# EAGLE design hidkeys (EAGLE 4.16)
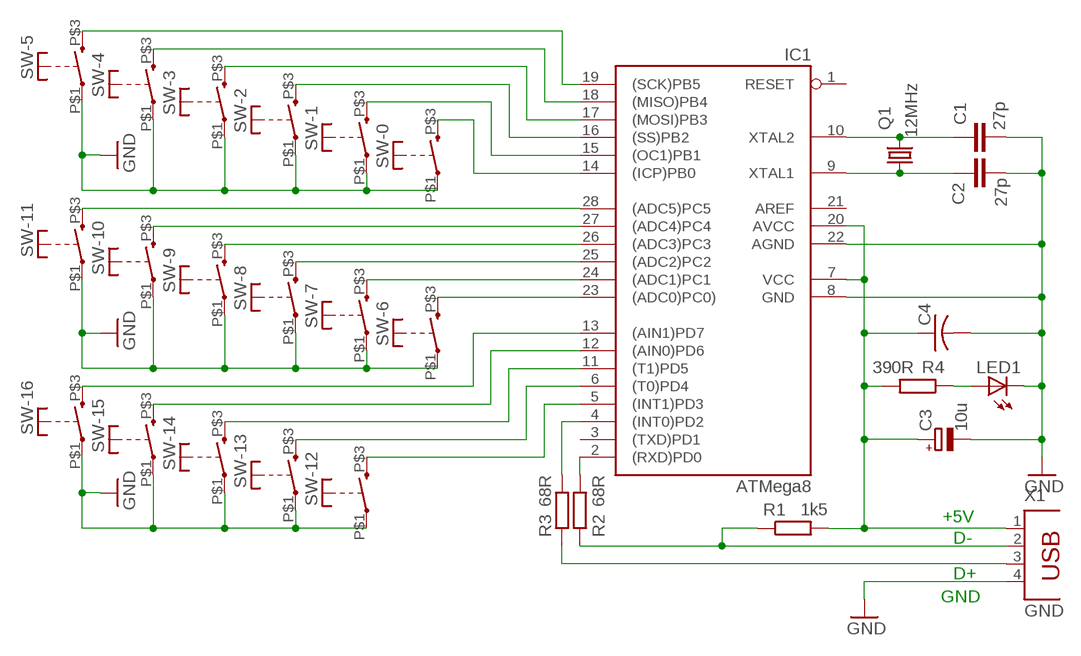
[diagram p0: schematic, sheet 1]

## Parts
C1  27p  C-EU025-024X044  [C025-024X044]
C2  27p  C-EU025-024X044  [C025-024X044]
C3  10u  CPOL-EUE2.5-5  [E2,5-5]
C4  C-US025-024X044  [C025-024X044]
IC1  ATMega8  AT90S4433P  [DIL28-3]
LED1  LED3MM  [LED3MM]
Q1  12MHz  CRYTALHC49S  [HC49/S]
R1  1k5  R-EU_0204/5  [0204/5]
R2  68R  R-EU_0204/5  [0204/5]
R3  68R  R-EU_0204/5  [0204/5]
R4  390R  R-EU_0204/5  [0204/5]
SW-0  DT  [AKI-DIP-SW]
SW-1  DT  [AKI-DIP-SW]
SW-2  DT  [AKI-DIP-SW]
SW-3  DT  [AKI-DIP-SW]
SW-4  DT  [AKI-DIP-SW]
SW-5  DT  [AKI-DIP-SW]
SW-6  DT  [AKI-DIP-SW]
SW-7  DT  [AKI-DIP-SW]
SW-8  DT  [AKI-DIP-SW]
SW-9  DT  [AKI-DIP-SW]
SW-10  DT  [AKI-DIP-SW]
SW-11  DT  [AKI-DIP-SW]
SW-12  DT  [AKI-DIP-SW]
SW-13  DT  [AKI-DIP-SW]
SW-14  DT  [AKI-DIP-SW]
SW-15  DT  [AKI-DIP-SW]
SW-16  DT  [AKI-DIP-SW]
X1  GND  PN61729  [PN61729]

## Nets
GND: C1.2 C2.2 C3.- C4.2 IC1.8(GND) IC1.22(AGND) LED1.K(C) SW-0.P$1(P) SW-1.P$1(P) SW-2.P$1(P) SW-3.P$1(P) SW-4.P$1(P) SW-5.P$1(P) SW-6.P$1(P) SW-7.P$1(P) SW-8.P$1(P) SW-9.P$1(P) SW-10.P$1(P) SW-11.P$1(P) SW-12.P$1(P) SW-13.P$1(P) SW-14.P$1(P) SW-15.P$1(P) SW-16.P$1(P) X1.4
N$1: IC1.19((SCK)PB5) SW-5.P$3(S)
N$2: IC1.18((MISO)PB4) SW-4.P$3(S)
N$4: IC1.16((SS)PB2) SW-2.P$3(S)
N$5: IC1.15((OC1)PB1) SW-1.P$3(S)
N$6: IC1.14((ICP)PB0) SW-0.P$3(S)
N$7: IC1.28((ADC5)PC5) SW-11.P$3(S)
N$8: IC1.27((ADC4)PC4) SW-10.P$3(S)
N$9: IC1.26((ADC3)PC3) SW-9.P$3(S)
N$10: IC1.25((ADC2)PC2) SW-8.P$3(S)
N$11: IC1.24((ADC1)PC1) SW-7.P$3(S)
N$12: IC1.23((ADC0)PC0)) SW-6.P$3(S)
N$13: IC1.13((AIN1)PD7) SW-16.P$3(S)
N$14: IC1.12((AIN0)PD6) SW-15.P$3(S)
N$15: IC1.11((T1)PD5) SW-14.P$3(S)
N$16: IC1.6((T0)PD4) SW-13.P$3(S)
N$17: IC1.5((INT1)PD3) SW-12.P$3(S)
N$18: R1.1 R2.1 X1.2
N$19: R3.1 X1.3
N$20: IC1.4((INT0)PD2) R3.2
N$21: C1.1 IC1.10(XTAL2) Q1.2
N$22: C2.1 IC1.9(XTAL1) Q1.1
N$23: IC1.2((RXD)PD0) R2.2
N$24: LED1.A R4.1
N$26: IC1.17((MOSI)PB3) SW-3.P$3(S)
VCC: C3.+ C4.1 IC1.7(VCC) IC1.20(AVCC) R1.2 R4.2 X1.1
Unconnected: IC1.1(RESET) IC1.3((TXD)PD1)

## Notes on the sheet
- +5V
- D-
- D+
- GND

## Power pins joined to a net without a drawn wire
AREF: IC1.21(AREF)

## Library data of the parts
C1 C2 = rcl:C-EU: CAPACITOR, European symbol
C3 = rcl:CPOL-EU: POLARIZED CAPACITOR, European symbol
C4 = 05 myrcl:C-US: CAPACITOR, American symbol
IC1 = atmel:AT90S4433: MICROCONTROLLER 4 Kbytes FLASH 128 bytes SRAM 256 bytes EEPROM UART 6-channel 10 bit ADC
LED1 = 35 led:LED: LED
Q1 = crystal:CRYTAL: CRYSTAL
R1-R4 = rcl:R-EU_: RESISTOR, European symbol
SW-0 SW-1-SW-16 = 01 MyLibs:DT: ITT SWITCH
X1 = con-berg:PN61729: BERG USB connector

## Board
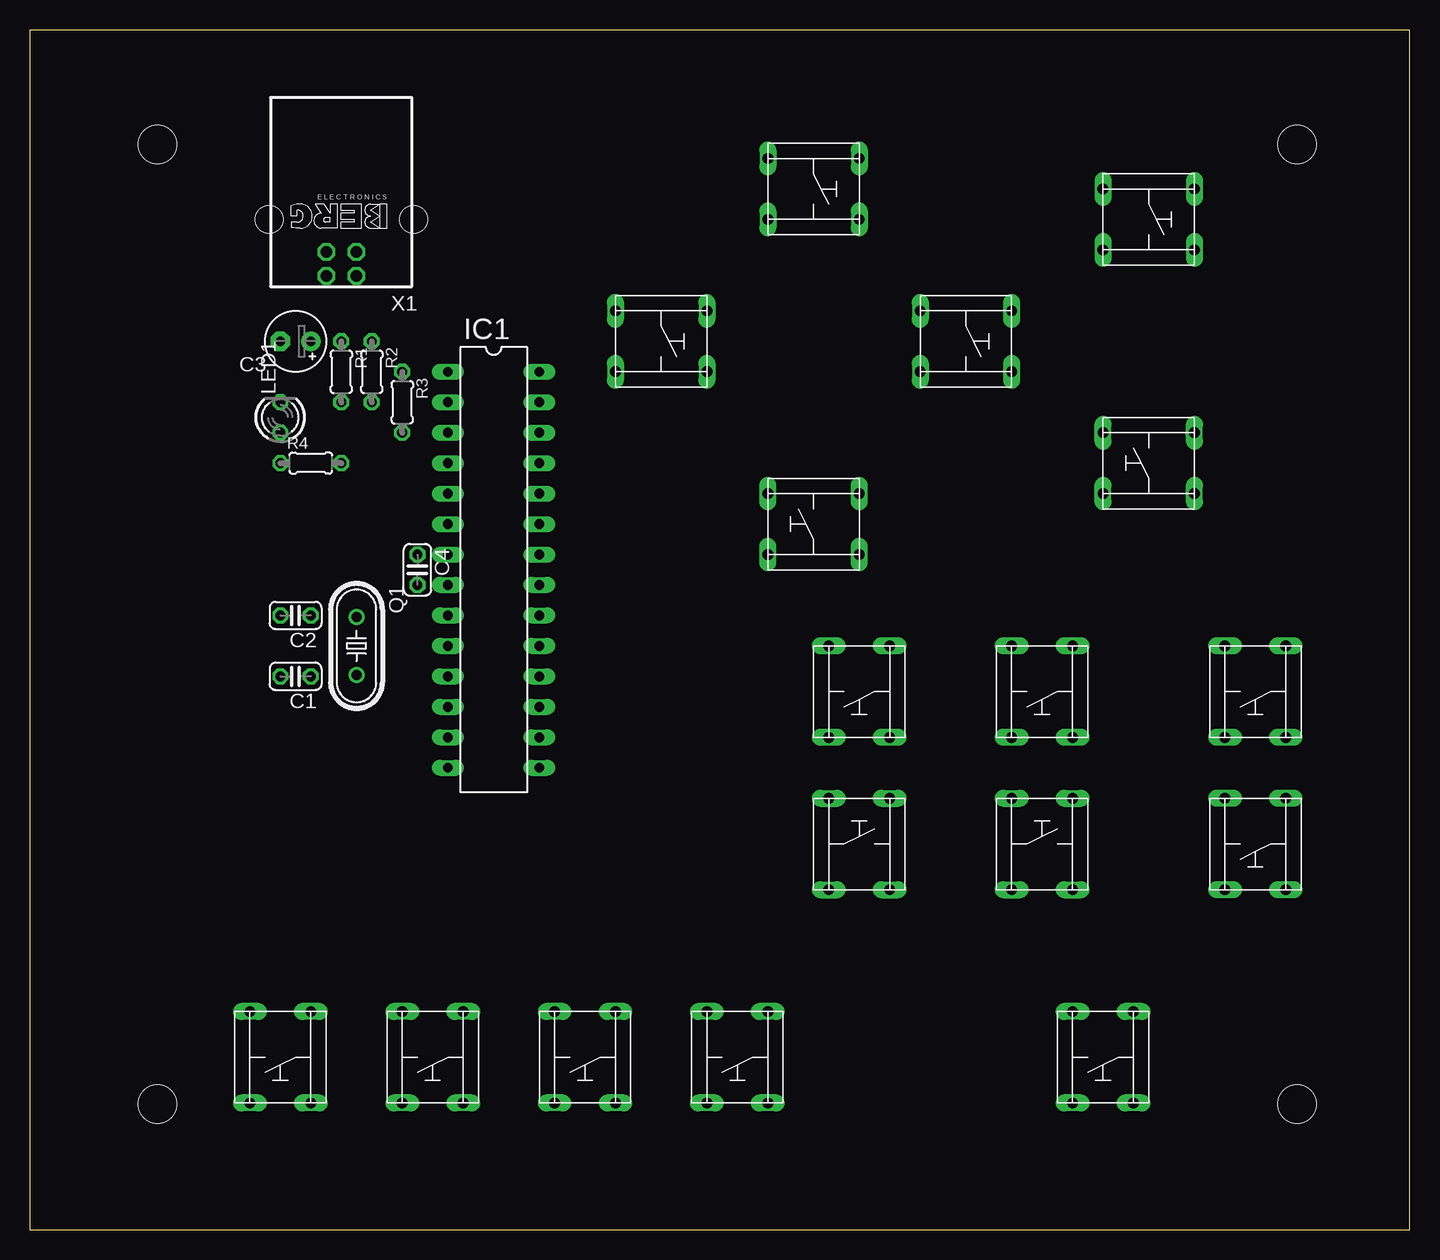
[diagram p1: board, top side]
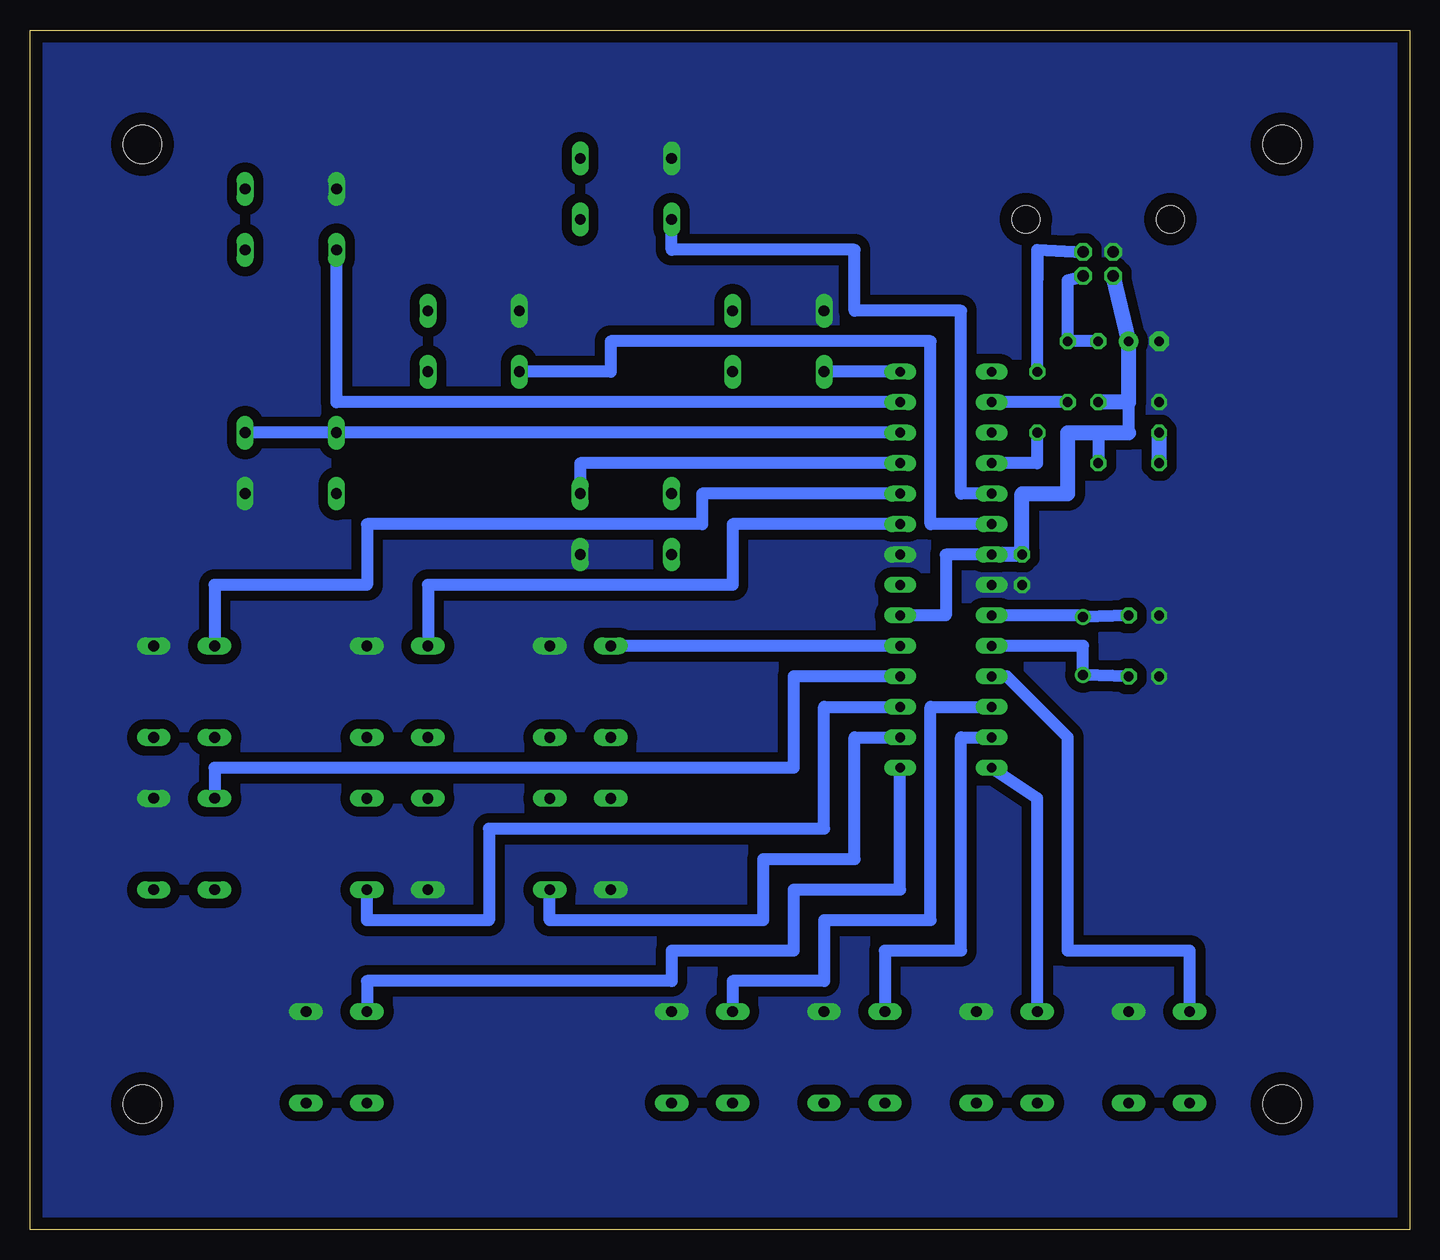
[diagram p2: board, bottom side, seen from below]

Size 115 x 100 mm. Coordinates in mm from the lower left corner, seen from the top.
Outline: 0,0 115,0 115,100 0,100 0,0
Copper layers (1*16): Top 0.035mm / dielectric 1.5mm / Bottom 0.035mm
Design rules "default": minimum track width 10mil, minimum drill 24mil, track to track 8mil, track to pad 8mil, pad to pad 8mil, via to via 8mil, smd to smd 8mil, copper to edge 40mil, drill to drill 8mil, minimum pad ring 10mil, minimum via ring 8mil, stop-mask expansion 4mil, vias tented up to drill 0mil, thermal gap 10mil
Holes 3.2 mm at 10.63,90.47 10.63,10.47 105.63,90.47 105.63,10.47

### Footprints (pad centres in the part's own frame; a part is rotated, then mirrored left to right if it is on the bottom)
C025-024X044 = drill 0.813 octagon: 1 -1.27,0; 2 1.27,0
E2,5-5 = drill 0.813 pad 1.6 round: + -1.27,0 | drill 0.813 pad 1.6 octagon: - 1.27,0
DIL28-3 = drill 0.813 long: 1 -16.51,-3.81; 2 -13.97,-3.81; 3 -11.43,-3.81; 4 -8.89,-3.81; 5 -6.35,-3.81; 6 -3.81,-3.81; 7 -1.27,-3.81; 8 1.27,-3.81; 9 3.81,-3.81; 10 6.35,-3.81; 11 8.89,-3.81; 12 11.43,-3.81; 13 13.97,-3.81; 14 16.51,-3.81; 15 16.51,3.81; 16 13.97,3.81; 17 11.43,3.81; 18 8.89,3.81; 19 6.35,3.81; 20 3.81,3.81; 21 1.27,3.81; 22 -1.27,3.81; 23 -3.81,3.81; 24 -6.35,3.81; 25 -8.89,3.81; 26 -11.43,3.81; 27 -13.97,3.81; 28 -16.51,3.81
LED3MM = drill 0.813 octagon: A -1.27,0; K 1.27,0
HC49/S = drill 0.813 round: 1 -2.413,0; 2 2.413,0
0204/5 = drill 0.813 octagon: 1 -2.54,0; 2 2.54,0
AKI-DIP-SW = drill 0.9 long: P$1 -2.54,2.54; P$2 5.08,2.54; P$3 -2.54,-2.54; P$4 5.08,-2.54
PN61729 = drill 0.95 octagon: 1 1.25,4.71; 2 -1.25,4.71; 3 -1.25,2.71; 4 1.25,2.71 | hole 2.3: -6.02,0; 6.02,0

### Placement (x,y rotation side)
C1  22.14,46.11 180 top
C2  22.14,51.19 180 top
C3  22.14,74.05 180 top
C4  32.3,55 270 top
IC1  38.65,55 270 top
LED1  20.87,67.7 90 top
Q1  27.22,48.65 270 top
R1  25.95,71.51 270 top
R2  28.49,71.51 270 top
R3  31.03,68.97 270 top
R4  23.41,63.89 0 top
SW-0  33.57,15.63 270 top
SW-1  89.45,15.63 270 top
SW-2  69.13,30.87 90 top
SW-3  84.37,30.87 90 top
SW-4  102.15,33.41 270 top
SW-5  69.13,46.11 270 top
SW-6  84.37,46.11 270 top
SW-7  102.15,46.11 270 top
SW-8  66.59,58.81 180 top
SW-9  94.53,63.89 180 top
SW-10  91.99,84.21 0 top
SW-11  51.35,74.05 0 top
SW-12  64.05,86.75 0 top
SW-13  76.75,74.05 0 top
SW-14  20.87,15.63 270 top
SW-15  58.97,15.63 270 top
SW-16  46.27,15.63 270 top
X1  25.95,84.21 180 top

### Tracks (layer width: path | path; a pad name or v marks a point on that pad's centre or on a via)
GND
  pour Bottom (isolate 0.813, no thermals): -1.99,101.99 117.39,101.99 117.39,-2.15 -1.99,-2.15
N$1
  Bottom 1.016: IC1.19 SW-5.P$3
N$2
  Bottom 1.016: IC1.18 51.35,46.11 51.35,38.49 99.61,38.49 SW-4.P$3
N$4
  Bottom 1.016: IC1.16 46.27,41.03 46.27,30.87 53.89,30.87 53.89,25.79 71.67,25.79 SW-2.P$3
N$5
  Bottom 1.016: IC1.15 42.46,28.33 51.35,28.33 51.35,23.25 61.51,23.25 61.51,20.71 86.91,20.71 SW-1.P$3
N$6
  Bottom 1.016: IC1.14 31.03,35.95 SW-0.P$3
N$7
  Bottom 1.016: IC1.28 SW-11.P$3
N$8
  Bottom 1.016: IC1.27 89.45,68.97 SW-10.P$3
N$9
  Bottom 1.016: IC1.26 SW-9.P$3
N$10
  Bottom 1.016: SW-8.P$3 69.13,63.89 IC1.25
N$11
  Bottom 1.016: IC1.24 58.97,61.35 58.97,58.81 86.91,58.81 86.91,53.73 99.61,53.73 SW-7.P$3
N$12
  Bottom 1.016: IC1.23 56.43,58.81 56.43,53.73 81.83,53.73 SW-6.P$3
N$13
  Bottom 1.016: IC1.13 37.38,41.03 37.38,23.25 43.73,23.25 SW-16.P$3
N$14
  Bottom 1.016: IC1.12 39.92,43.57 39.92,25.79 48.81,25.79 48.81,20.71 56.43,20.71 SW-15.P$3
N$15
  Bottom 1.016: IC1.11 33.57,46.11 28.49,41.03 28.49,23.25 18.33,23.25 SW-14.P$3
N$16
  Bottom 1.016: IC1.6 39.92,58.81 39.92,74.05 66.59,74.05 66.59,71.51 SW-13.P$3
N$17
  Bottom 1.016: IC1.5 37.38,61.35 37.38,76.59 46.27,76.59 46.27,81.67 61.51,81.67 SW-12.P$3
N$18
  Bottom 1.016: R1.1 R2.1 28.49,79.13 X1.2
N$19
  Bottom 1.016: R3.1 31.03,81.67 | 31.03,81.67 31.03,79.13 | 31.03,81.67 X1.3
N$20
  Bottom 1.016: R3.2 31.03,63.89 IC1.4
N$21
  Bottom 1.016: IC1.10 27.22,48.65 Q1.2 C1.1
N$22
  Bottom 1.016: IC1.9 27.22,51.19 Q1.1 C2.1
N$23
  Bottom 1.016: R2.2 IC1.2
N$24
  Bottom 1.27: R4.1 LED1.A
N$26
  Bottom 1.016: IC1.17 48.81,43.57 48.81,33.41 76.75,33.41 76.75,25.79 86.91,25.79 SW-3.P$3
VCC
  Bottom 1.016: IC1.7 38.65,56.27 38.65,51.19 IC1.20 | 23.41,66.43 23.41,68.97 | 25.95,66.43 R4.2
  Bottom 1.27: IC1.7 C4.1 32.3,61.35 28.49,61.35 28.49,66.43 25.95,66.43 23.41,66.43 | R1.2 23.41,68.97 C3.+ X1.1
